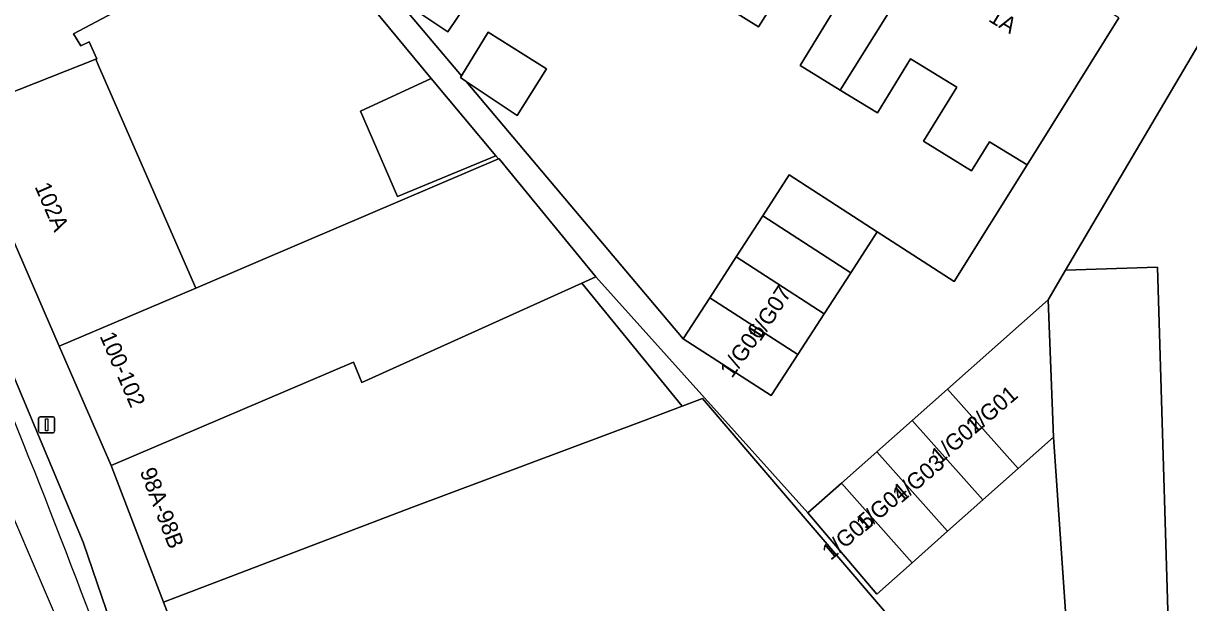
# Model space of a CAD drawing. Extents: x 160856 to 161310, y 384024 to 384878.
# Drawn here: x 161119.8 to 161191.7, y 384335.9 to 384371.7 of the extents above; entities that cross this region are included whole.
import ezdxf

# ---------------------------------------------------------------- set-up
doc = ezdxf.new("R2010")
doc.units = 0
for name, color, linetype in [('IMGEO_Erf', 7, 'Continuous'), ('IMGEO_Fietspad_gesloten', 7, 'Continuous'), ('IMGEO_Fietspad_open', 7, 'Continuous'), ('IMGEO_Lichtmast', 7, 'Continuous'), ('IMGEO_Pand', 7, 'Continuous'), ('IMGEO_Pand_nummerreeks', 7, 'Continuous'), ('IMGEO_Voetpad_open', 7, 'Continuous')]:
    doc.layers.add(name, color=color, linetype=linetype)

msp = doc.modelspace()

# ---------------------------------------------------------------- linework, layer by layer
at = {"layer": 'IMGEO_Erf'}
for points in [[(161144.963, 384368.273), (161136.648, 384378.337), (161122.916, 384371.04), (161123.357, 384370.305), (161123.867, 384370.542), (161124.335, 384369.483), (161124.287, 384369.464), (161124.436, 384369.122), (161130.366, 384355.541), (161130.449, 384355.35), (161137.118, 384358.195), (161149.119, 384363.315), (161148.95, 384363.508), (161142.882, 384361.001), (161140.6, 384366.267)], [(161142.654, 384373.398), (161144.528, 384376.195), (161147.864, 384373.96), (161145.99, 384371.163)]]:
    msp.add_lwpolyline(points, close=True, dxfattribs=at)
for points in [[(161166.879, 384374.249), (161165.143, 384371.47), (161162.099, 384373.371)], [(161142.654, 384373.398), (161146.826, 384368.45), (161148.473, 384371.131), (161152.064, 384368.884), (161150.256, 384365.995), (161147.12, 384368.101), (161160.505, 384352.226), (161162.139, 384354.752), (161163.772, 384357.278), (161165.406, 384359.805), (161167.04, 384362.331), (161172.461, 384358.825), (161177.201, 384355.76), (161181.697, 384362.955), (161179.376, 384364.381), (161178.276, 384362.591), (161175.322, 384364.407), (161177.368, 384367.737), (161174.52, 384369.487), (161172.472, 384366.154), (161170.177, 384367.564), (161167.7, 384369.086), (161169.779, 384372.467)], [(161193.025, 384371.653), (161184.071, 384356.465), (161189.735, 384356.643), (161190.59, 384328.638), (161188.742, 384328.511), (161187.744, 384328.443), (161187.765, 384328.062), (161187.926, 384325.082), (161184.799, 384324.913), (161185.126, 384319.785), (161185.36, 384315.902), (161185.661, 384310.911), (161187.145, 384310.814), (161188.793, 384310.655), (161192.181, 384310.284)], [(161184.31, 384331.83), (161183.32, 384346.153), (161181.144, 384344.218), (161178.968, 384342.283), (161176.792, 384340.349), (161174.616, 384338.414), (161172.44, 384336.479), (161168.177, 384341.49), (161155.109, 384356.045), (161154.245, 384355.654), (161154.427, 384355.432), (161160.436, 384348.067), (161161.693, 384348.538), (161173.878, 384334.3)]]:
    msp.add_lwpolyline(points, dxfattribs=at)
at = {"layer": 'IMGEO_Fietspad_gesloten'}
msp.add_lwpolyline([(161114.316, 384358.942), (161112.031, 384357.896), (161127.696, 384321.331), (161130.392, 384305.052), (161130.473, 384295.252), (161130.552, 384285.673)], dxfattribs=at)
msp.add_arc((160641.225, 384153.666), 515.706, 20.27677, 23.45619, dxfattribs=at)
at = {"layer": 'IMGEO_Fietspad_open'}
for points in [[(161123.508, 384339.684), (161115.245, 384359.367), (161114.316, 384358.942)], [(161125.78, 384333.006), (161123.508, 384339.684)]]:
    msp.add_lwpolyline(points, dxfattribs=at)
msp.add_arc((160641.225, 384153.666), 515.706, 20.27677, 23.45619, dxfattribs=at)
at = {"layer": 'IMGEO_Lichtmast'}
for p, q in [((161120.754, 384346.52), (161120.754, 384347.32)), ((161120.754, 384347.32), (161120.754, 384346.52)), ((161120.854, 384347.42), (161121.644, 384347.42)), ((161121.644, 384347.42), (161120.854, 384347.42)), ((161121.744, 384347.32), (161121.744, 384346.52)), ((161121.744, 384346.52), (161121.744, 384347.32)), ((161121.644, 384346.42), (161120.854, 384346.42)), ((161120.854, 384346.42), (161121.644, 384346.42))]:
    msp.add_line(p, q, dxfattribs=at)
msp.add_lwpolyline([(161121.174, 384347.295), (161121.324, 384347.295), (161121.324, 384346.545), (161121.174, 384346.545), (161121.174, 384347.295)], dxfattribs=at)
for centre, start, end in [((161120.854, 384347.32), 90, 180), ((161120.854, 384347.32), 90, 180), ((161121.644, 384347.32), 0, 90), ((161121.644, 384347.32), 360, 90), ((161120.854, 384346.52), 180, 270), ((161120.854, 384346.52), 180, 270), ((161121.644, 384346.52), 270, 0), ((161121.644, 384346.52), 270, 0)]:
    msp.add_arc(centre, 0.1, start, end, dxfattribs=at)
at = {"layer": 'IMGEO_Pand'}
for points in [[(161166.879, 384374.249), (161170.985, 384380.821), (161165.417, 384384.3), (161163.423, 384381.055), (161161.016, 384382.534), (161160.622, 384382.776), (161159.968, 384381.713), (161156.355, 384375.834), (161160.615, 384373.216), (161161.623, 384372.596), (161162.099, 384373.371), (161165.143, 384371.47)], [(161122.916, 384371.04), (161136.648, 384378.337), (161136.053, 384379.045), (161133.875, 384381.638), (161125.508, 384377.2), (161113.323, 384370.829), (161115.785, 384366.119), (161124.287, 384369.464), (161124.335, 384369.483), (161123.867, 384370.542), (161123.357, 384370.305)], [(161166.879, 384374.249), (161169.779, 384372.467), (161167.7, 384369.086), (161170.177, 384367.564), (161176.362, 384377.462), (161170.985, 384380.821)], [(161170.177, 384367.564), (161172.472, 384366.154), (161174.52, 384369.487), (161177.368, 384367.737), (161175.322, 384364.407), (161178.276, 384362.591), (161179.376, 384364.381), (161181.697, 384362.955), (161184.709, 384367.775), (161187.358, 384372.015), (161185.155, 384373.42), (161186.253, 384375.201), (161183.21, 384377.056), (161181.501, 384374.251), (161176.362, 384377.462)], [(161142.654, 384373.398), (161145.99, 384371.163), (161147.864, 384373.96), (161144.528, 384376.195)], [(161146.826, 384368.45), (161146.76, 384368.343), (161147.12, 384368.101), (161150.256, 384365.995), (161152.064, 384368.884), (161148.473, 384371.131)], [(161124.436, 384369.122), (161124.287, 384369.464), (161115.785, 384366.119), (161122.031, 384351.759), (161130.449, 384355.35), (161130.366, 384355.541)], [(161144.963, 384368.273), (161140.6, 384366.267), (161142.882, 384361.001), (161148.95, 384363.508)], [(161154.245, 384355.654), (161155.109, 384356.045), (161149.787, 384362.55), (161149.15, 384363.328), (161149.119, 384363.315), (161137.118, 384358.195), (161130.449, 384355.35), (161122.031, 384351.759), (161125.225, 384344.414), (161140.168, 384350.79), (161140.691, 384349.519)], [(161170.828, 384356.299), (161172.461, 384358.825), (161167.04, 384362.331), (161165.406, 384359.805)], [(161163.772, 384357.278), (161169.194, 384353.772), (161170.828, 384356.299), (161165.406, 384359.805)], [(161163.772, 384357.278), (161162.139, 384354.752), (161167.56, 384351.246), (161169.194, 384353.772)], [(161188.742, 384328.511), (161190.59, 384328.638), (161189.735, 384356.643), (161184.071, 384356.465), (161183.004, 384354.629), (161183.32, 384346.153), (161184.31, 384331.83), (161184.604, 384328.227), (161187.744, 384328.443)], [(161160.436, 384348.067), (161154.427, 384355.432), (161154.245, 384355.654), (161140.691, 384349.519), (161140.168, 384350.79), (161125.225, 384344.414), (161128.456, 384335.969), (161143.695, 384341.799), (161158.044, 384347.171)], [(161167.56, 384351.246), (161162.139, 384354.752), (161160.505, 384352.226), (161165.927, 384348.72)], [(161183.004, 384354.629), (161176.786, 384349.119), (161181.144, 384344.218), (161183.32, 384346.153)], [(161178.968, 384342.283), (161181.144, 384344.218), (161176.786, 384349.119), (161174.607, 384347.188)], [(161146.843, 384333.693), (161150.199, 384332.38), (161158.754, 384332.896), (161173.085, 384333.395), (161173.878, 384334.3), (161161.693, 384348.538), (161160.436, 384348.067), (161158.044, 384347.171), (161143.695, 384341.799), (161128.456, 384335.969), (161131.631, 384327.67), (161133.903, 384328.57), (161136.28, 384329.511)], [(161178.968, 384342.283), (161174.607, 384347.188), (161172.428, 384345.257), (161176.792, 384340.349)], [(161174.616, 384338.414), (161176.792, 384340.349), (161172.428, 384345.257), (161170.249, 384343.326)], [(161174.616, 384338.414), (161170.249, 384343.326), (161168.177, 384341.49), (161172.44, 384336.479)]]:
    msp.add_lwpolyline(points, close=True, dxfattribs=at)
at = {"layer": 'IMGEO_Voetpad_open'}
for points in [[(161132.777, 384307.558), (161136.93, 384307.974), (161135.512, 384309.231), (161135.057, 384316.787), (161134.682, 384321.856), (161134.328, 384327.656), (161133.903, 384328.57), (161131.631, 384327.67), (161128.456, 384335.969), (161125.225, 384344.414), (161122.031, 384351.759), (161115.785, 384366.119), (161113.323, 384370.829), (161111.124, 384375.035), (161109.392, 384378.348), (161108.604, 384379.661), (161104.277, 384386.876)], [(161136.648, 384378.337), (161144.963, 384368.273), (161148.95, 384363.508), (161149.119, 384363.315), (161149.15, 384363.328), (161149.787, 384362.55), (161155.109, 384356.045), (161168.177, 384341.49), (161170.249, 384343.326), (161172.428, 384345.257), (161174.607, 384347.188), (161176.786, 384349.119), (161183.004, 384354.629), (161184.071, 384356.465), (161193.025, 384371.653), (161193.268, 384371.981)], [(161187.358, 384372.015), (161184.709, 384367.775), (161181.697, 384362.955), (161177.201, 384355.76), (161172.461, 384358.825), (161170.828, 384356.299), (161169.194, 384353.772), (161167.56, 384351.246), (161165.927, 384348.72), (161160.505, 384352.226), (161147.12, 384368.101), (161146.76, 384368.343), (161146.826, 384368.45), (161142.654, 384373.398)], [(161115.245, 384359.367), (161123.508, 384339.684), (161125.78, 384333.006)]]:
    msp.add_lwpolyline(points, dxfattribs=at)

# ---------------------------------------------------------------- texts
at = {"layer": 'IMGEO_Pand_nummerreeks'}
for s, rotation, p in [('1A', 328.90612, (161179.264, 384371.844)), ('102A', 293.50825, (161120.494, 384361.611)), ('1/G07', 57.09726, (161165.245, 384352.003)), ('1/G06', 54.717, (161163.505, 384349.749)), ('100-102', 293.50252, (161124.502, 384352.394)), ('1/G01', 40.57944, (161178.455, 384346.288)), ('1/G02', 40.57944, (161176.304, 384344.446)), ('1/G03', 40.57944, (161173.935, 384342.047)), ('98A-98B', 290.74086, (161126.982, 384344.053)), ('1/G04', 40.57944, (161171.692, 384340.28)), ('1/G05', 40.57944, (161169.591, 384338.514))]:
    msp.add_text(s, height=1, rotation=rotation, dxfattribs=at).set_placement(p)

doc.saveas('drawing.dxf')
